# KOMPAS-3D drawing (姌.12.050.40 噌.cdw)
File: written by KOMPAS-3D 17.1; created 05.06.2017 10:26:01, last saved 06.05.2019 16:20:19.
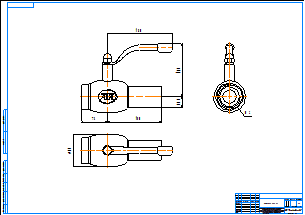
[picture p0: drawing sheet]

Sheet 1: A1, landscape

Title block, sheet 1: name: КШ.12.050.40 рс; material: Внимание! Данный продукт является объектом авторского права ООО «Торговый Дом АДЛ». / Запрещается изменение, копирование, распространение / (в том числе путем копирования на другие сайты и ресурсы в Интернете) / или любое иное использование информации и объектов без предварительного / согласия правообладателя (ООО «Торговый Дом АДЛ»).; sheets: 1; organisation: ООО "Торговый дом АДЛ"; sheet format: A1; stored path: C:\Users\kka\KOMPAS_Work\Модели кранов для исследований\Все краники\Редуцированный резьба-сварка ШК БИВАЛ\КШ.02.015.40 рс.cdw

Views: Вид 1, Проекционный вид 2, Проекционный вид 3
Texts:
  Klimkovich
  ADL
Dimensions and other numbers on the sheet: 180; 73; 150; 148; 28,5; 89; 1:1; 1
